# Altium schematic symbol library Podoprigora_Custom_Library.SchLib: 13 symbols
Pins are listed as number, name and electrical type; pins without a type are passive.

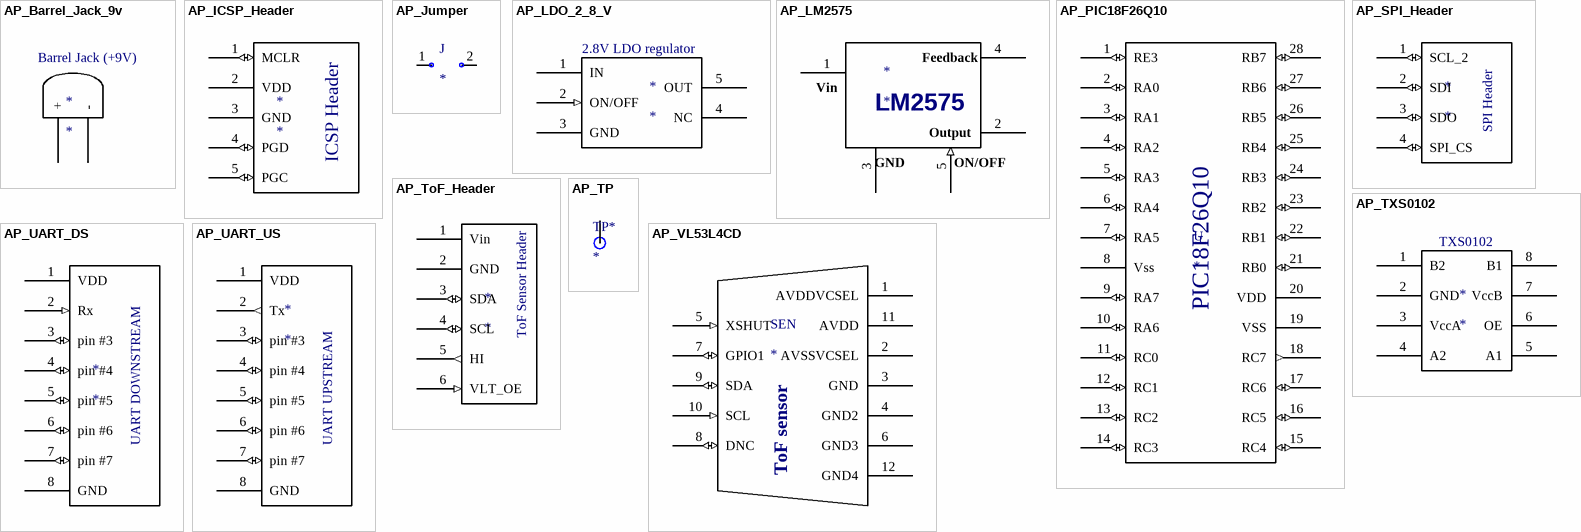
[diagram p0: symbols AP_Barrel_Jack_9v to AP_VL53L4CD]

## AP_Barrel_Jack_9v
designator *
pins: 1 + (power), 1 - (power)

## AP_ICSP_Header
designator *
Header for the Microchip Snap
pins: 1 MCLR (io), 2 VDD (power), 3 GND (power), 4 PGD (io), 5 PGC (io)

## AP_Jumper
designator J
pins: 1, 2

## AP_LDO_2_8_V
designator *
pins: 1 IN (power), 2 ON/OFF (in), 3 GND (power), 4 NC, 5 OUT (power)

## AP_LM2575
designator *
pins: 1 Vin, 2 Output, 3 GND, 4 Feedback, 5 ON/OFF (in)

## AP_PIC18F26Q10
designator U
PIC18F26Q10 represented as a library element
pins: 1 RE3 (io), 2 RA0 (io), 3 RA1 (io), 4 RA2 (io), 5 RA3 (io), 6 RA4 (io), 7 RA5 (io), 8 Vss (power), 9 RA7 (io), 10 RA6 (io), 11 RC0 (io), 12 RC1 (io), 13 RC2 (io), 14 RC3 (io), 15 RC4 (io), 16 RC5 (io), 17 RC6 (io), 18 RC7 (out), 19 VSS (power), 20 VDD, 21 RB0 (io), 22 RB1 (io), 23 RB2 (io), 24 RB3 (io), 25 RB4 (io), 26 RB5 (io), 27 RB6 (io), 28 RB7 (io)

## AP_SPI_Header
designator *
pins: 1 SCL_2 (io), 2 SDI (io), 3 SDO (io), 4 SPI_CS (io)

## AP_ToF_Header
designator *
pins: 1 Vin, 2 GND, 3 SDA (io), 4 SCL (io), 5 HI (out), 6 VLT_OE (in)

## AP_TP
designator TP*
pins: 31

## AP_TXS0102
designator *
pins: 1 B2, 2 GND, 3 VccA, 4 A2, 5 A1, 6 OE, 7 VccB, 8 B1

## AP_UART_DS
designator *
pins: 1 VDD (power), 2 Rx (in), 3 pin #3 (io), 4 pin #4 (io), 5 pin #5 (io), 6 pin #6 (io), 7 pin #7 (io), 8 GND (power)

## AP_UART_US
designator *
pins: 1 VDD (power), 2 Tx (out), 3 pin #3 (io), 4 pin #4 (io), 5 pin #5 (io), 6 pin #6 (io), 7 pin #7 (io), 8 GND (power)

## AP_VL53L4CD
designator SEN
Tof sensor type VL53L4CD
pins: 1 AVDDVCSEL (power), 2 AVSSVCSEL (power), 3 GND (power), 4 GND2 (power), 5 XSHUT (in), 6 GND3 (power), 7 GPIO1 (io), 8 DNC (io), 9 SDA (io), 10 SCL (in), 11 AVDD (power), 12 GND4 (power)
